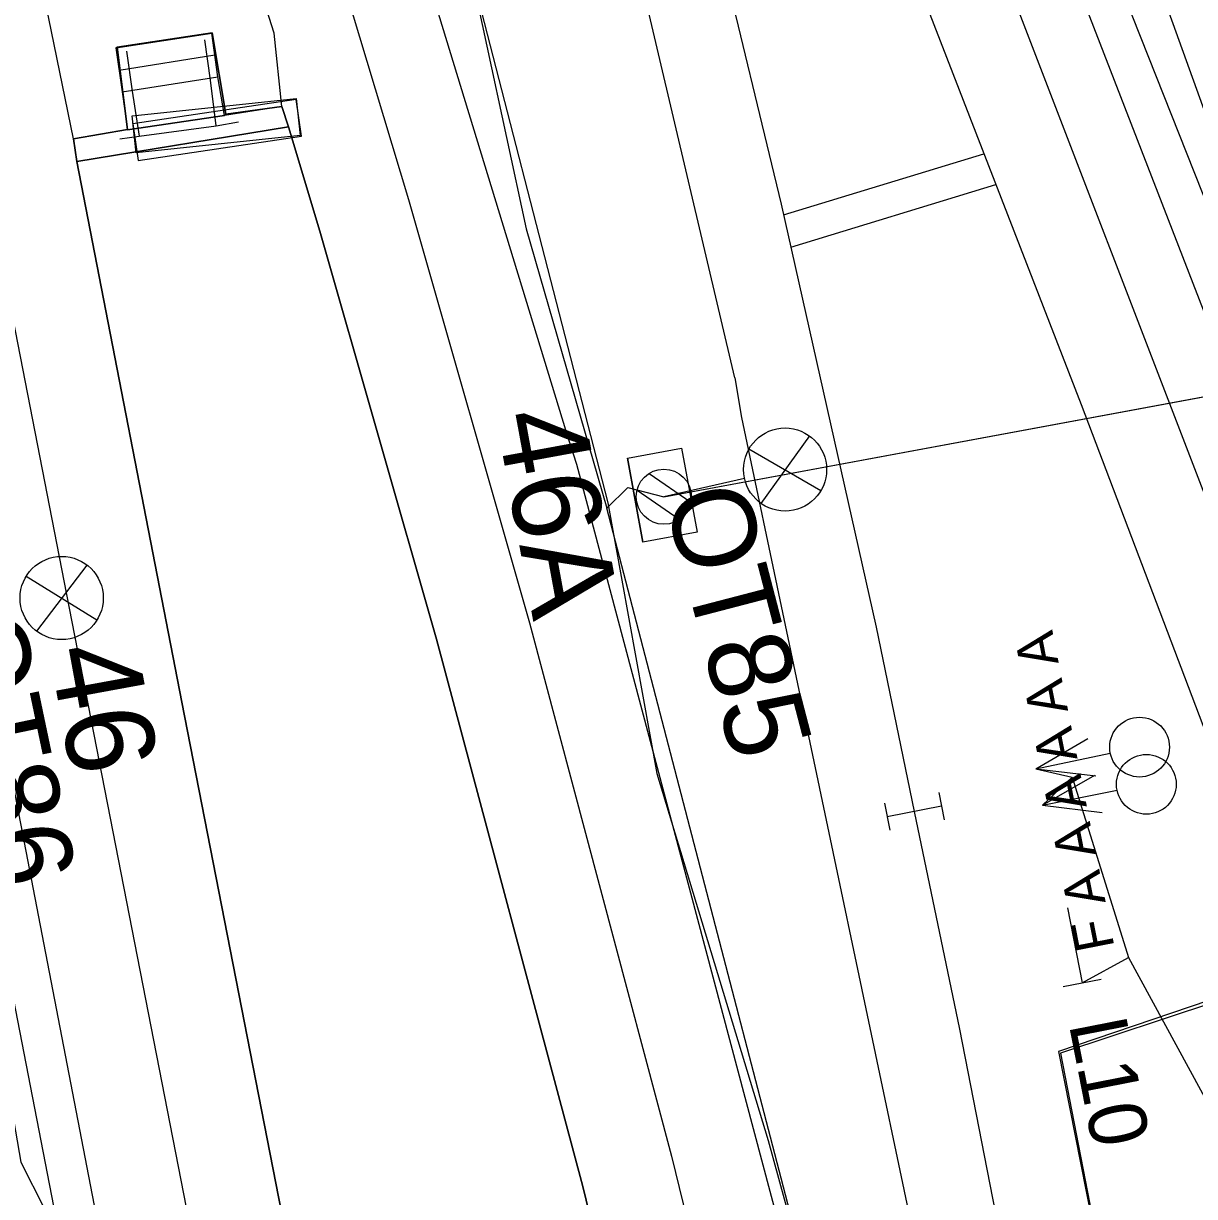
# Model space of a CAD drawing. Extents: x -545736 to -544888, y -1122892 to -1119128.
# Drawn here: x -545201.67 to -545180.42, y -1121712.96 to -1121691.68 of the extents above; entities that cross this region are included whole.
import ezdxf

# ---------------------------------------------------------------- set-up
doc = ezdxf.new("R2010")
doc.units = 0
for name, color, linetype in [('osvětlené plochy-hodnota-obrys', 7, 'Continuous'), ('Podbarveni_Komunikace', 7, 'Continuous'), ('Podbarveni_Nastupiste', 7, 'Continuous'), ('Vrstva 1 - Koleje', 7, 'Continuous'), ('Vrstva 11 - Trakce', 7, 'Continuous'), ('Vrstva 12 - Trakce zaklady', 7, 'Continuous'), ('Vrstva 13', 7, 'Continuous'), ('Vrstva 14_zastreseni a nastupiste', 7, 'Continuous'), ('Vrstva 16_plochy', 7, 'Continuous'), ('Vrstva 17_ploty - zabradli', 7, 'Continuous'), ('Vrstva 23 - PHS - pozemni - schody - eskalatory', 7, 'Continuous'), ('Vrstva 25', 7, 'Continuous'), ('Vrstva 26', 7, 'Continuous'), ('Vrstva 28 - zabzar', 7, 'Continuous'), ('Vrstva 3 - Lisy - Pocitaci body', 7, 'Continuous'), ('Vrstva 4 - Teren - stezky - prechody - plochy', 7, 'Continuous'), ('Vrstva 44', 7, 'Continuous'), ('Vrstva 6 - Navesti', 7, 'Continuous'), ('Vrstva 7 - Namezniky-vystroj', 7, 'Continuous')]:
    doc.layers.add(name, color=color, linetype=linetype)

msp = doc.modelspace()

# ---------------------------------------------------------------- linework, layer by layer
at = {"layer": 'osvětlené plochy-hodnota-obrys'}
msp.add_lwpolyline([(-545137.864, -1121889.42), (-545168.59, -1121731.992), (-545178.308, -1121699.721), (-545197.027, -1121652.528), (-545208.16, -1121619.35), (-545217.952, -1121591.114), (-545225.649, -1121565.547)], dxfattribs=at)
at = {"layer": 'Podbarveni_Komunikace'}
msp.add_lwpolyline([(-545180.039, -1121709.428), (-545180.163, -1121709.404), (-545182.89, -1121710.328), (-545181.985, -1121714.917)], dxfattribs=at)
at = {"layer": 'Podbarveni_Nastupiste'}
for p, q in [((-545196.294, -1121695.448), (-545196.861, -1121693.551)), ((-545194.179, -1121702.847), (-545196.294, -1121695.448)), ((-545198.798, -1121703.988), (-545196.89, -1121713.766))]:
    msp.add_line(p, q, dxfattribs=at)
for points in [[(-545196.861, -1121693.551), (-545200.703, -1121694.182), (-545198.798, -1121703.988)], [(-545189.161, -1121722.457), (-545191.523, -1121712.775), (-545194.179, -1121702.847)]]:
    msp.add_lwpolyline(points, dxfattribs=at)
at = {"layer": 'Vrstva 1 - Koleje'}
for points in [[(-545204.598, -1121683.045), (-545202.446, -1121694.084), (-545200.893, -1121702.036), (-545198.518, -1121714.179), (-545196.602, -1121723.995), (-545194.695, -1121733.769), (-545192.79, -1121743.532), (-545190.869, -1121753.385), (-545188.974, -1121763.101), (-545187.053, -1121772.965), (-545185.151, -1121782.729), (-545183.231, -1121792.594), (-545181.323, -1121802.379), (-545179.426, -1121812.108), (-545177.532, -1121821.821), (-545175.608, -1121831.705), (-545173.691, -1121841.53), (-545171.796, -1121851.251), (-545169.872, -1121861.126)], [(-545190.187, -1121685.59), (-545187.923, -1121694.959), (-545186.2, -1121702.627), (-545185.507, -1121705.971), (-545184.687, -1121709.924), (-545182.492, -1121721.163), (-545180.59, -1121730.931), (-545178.666, -1121740.784), (-545176.766, -1121750.544), (-545174.869, -1121760.278), (-545172.942, -1121770.162), (-545171.042, -1121779.908), (-545169.129, -1121789.7), (-545167.212, -1121799.555), (-545165.293, -1121809.36), (-545163.388, -1121819.134), (-545161.468, -1121828.982), (-545159.566, -1121838.742), (-545157.655, -1121848.546), (-545155.739, -1121858.373)], [(-545196.328, -1121689.408), (-545194.686, -1121694.87), (-545192.492, -1121702.549), (-545189.916, -1121712.225), (-545187.524, -1121721.986), (-545185.303, -1121731.906), (-545183.337, -1121741.604), (-545181.431, -1121751.413), (-545179.514, -1121761.238), (-545177.608, -1121771.007), (-545175.701, -1121780.793), (-545173.785, -1121790.62), (-545171.889, -1121800.35), (-545169.976, -1121810.166), (-545168.071, -1121819.938), (-545166.148, -1121829.808), (-545164.234, -1121839.613), (-545162.332, -1121849.377), (-545160.421, -1121859.17)], [(-545185.383, -1121691.101), (-545182.479, -1121698.59), (-545179.623, -1121706.109), (-545177.117, -1121713.199), (-545175.826, -1121717.114), (-545175.044, -1121719.485), (-545172.193, -1121729.1), (-545169.655, -1121738.82), (-545167.452, -1121748.582), (-545165.503, -1121758.451), (-545163.6, -1121768.21), (-545161.69, -1121777.988), (-545159.773, -1121787.837), (-545157.871, -1121797.594), (-545155.965, -1121807.383), (-545154.069, -1121817.086), (-545152.127, -1121827.047), (-545150.241, -1121836.711), (-545148.328, -1121846.526), (-545146.419, -1121856.308)]]:
    msp.add_lwpolyline(points, dxfattribs=at)
at = {"layer": 'Vrstva 11 - Trakce'}
for p, q in [((-545190.052, -1121700.262), (-545169.358, -1121696.433)), ((-545190.316, -1121699.842), (-545189.564, -1121700.36)), ((-545190.535, -1121700.146), (-545189.772, -1121700.672))]:
    msp.add_line(p, q, dxfattribs=at)
msp.add_circle((-545190.052, -1121700.262), 0.5, dxfattribs=at)
at = {"layer": 'Vrstva 12 - Trakce zaklady'}
for p, q in [((-545190.714, -1121699.563), (-545189.73, -1121699.382)), ((-545189.45, -1121700.906), (-545190.434, -1121701.087))]:
    msp.add_line(p, q, dxfattribs=at)
for points in [[(-545189.73, -1121699.382), (-545189.45, -1121700.906), (-545190.434, -1121701.087), (-545190.714, -1121699.563), (-545189.73, -1121699.382)], [(-545189.73, -1121699.382), (-545189.73, -1121699.382), (-545189.45, -1121700.906), (-545189.45, -1121700.906)], [(-545190.714, -1121699.563), (-545190.714, -1121699.563), (-545190.434, -1121701.087), (-545190.434, -1121701.087)]]:
    msp.add_lwpolyline(points, dxfattribs=at)
at = {"layer": 'Vrstva 13'}
for p, q in [((-545196.981, -1121693.185), (-545196.986, -1121693.19)), ((-545196.861, -1121693.551), (-545196.861, -1121693.551)), ((-545200.766, -1121693.77), (-545200.766, -1121693.77)), ((-545200.703, -1121694.182), (-545200.703, -1121694.182))]:
    msp.add_line(p, q, dxfattribs=at)
msp.add_lwpolyline([(-545200.703, -1121694.182), (-545196.861, -1121693.551), (-545196.981, -1121693.185), (-545198.025, -1121693.349), (-545199.783, -1121693.61), (-545200.766, -1121693.77)], close=True, dxfattribs=at)
for points in [[(-545198.025, -1121693.349), (-545198.002, -1121693.324), (-545196.981, -1121693.185), (-545196.861, -1121693.551)], [(-545200.703, -1121694.182), (-545200.766, -1121693.77), (-545199.786, -1121693.603), (-545199.783, -1121693.61)]]:
    msp.add_lwpolyline(points, dxfattribs=at)
at = {"layer": 'Vrstva 14_zastreseni a nastupiste'}
for p, q in [((-545196.861, -1121693.551), (-545196.861, -1121693.551)), ((-545200.703, -1121694.182), (-545200.703, -1121694.182))]:
    msp.add_line(p, q, dxfattribs=at)
msp.add_lwpolyline([(-545189.242, -1121752.936), (-545191.158, -1121743.114), (-545193.062, -1121733.349), (-545194.982, -1121723.565), (-545196.89, -1121713.766), (-545198.798, -1121703.988), (-545200.703, -1121694.182), (-545196.861, -1121693.551), (-545196.294, -1121695.448), (-545194.179, -1121702.847), (-545191.523, -1121712.775), (-545189.161, -1121722.457), (-545186.979, -1121732.216), (-545185.006, -1121741.979), (-545183.088, -1121751.748)], dxfattribs=at)
msp.add_lwpolyline([(-545189.242, -1121752.936), (-545191.158, -1121743.114), (-545193.062, -1121733.349), (-545194.982, -1121723.565), (-545196.89, -1121713.766), (-545198.798, -1121703.988), (-545200.703, -1121694.182), (-545196.861, -1121693.551), (-545196.294, -1121695.448), (-545194.179, -1121702.847), (-545191.523, -1121712.775), (-545189.161, -1121722.457), (-545186.979, -1121732.216), (-545185.006, -1121741.979), (-545183.088, -1121751.748)], dxfattribs=at)
at = {"layer": 'Vrstva 16_plochy'}
for points in [[(-545189.242, -1121752.936), (-545191.158, -1121743.114), (-545193.062, -1121733.349), (-545194.982, -1121723.565), (-545196.89, -1121713.766), (-545198.798, -1121703.988), (-545200.703, -1121694.182), (-545196.861, -1121693.551), (-545196.294, -1121695.448), (-545194.179, -1121702.847), (-545191.523, -1121712.775), (-545189.161, -1121722.457), (-545186.979, -1121732.216), (-545185.006, -1121741.979), (-545183.088, -1121751.748)], [(-545181.959, -1121714.966), (-545178.683, -1121714.378), (-545179.201, -1121712.924), (-545178.847, -1121712.802), (-545180.039, -1121709.428), (-545182.857, -1121710.357), (-545181.959, -1121714.966)]]:
    msp.add_lwpolyline(points, dxfattribs=at)
at = {"layer": 'Vrstva 17_ploty - zabradli'}
for p, q in [((-545198.175, -1121693.533), (-545197.772, -1121693.465)), ((-545199.922, -1121693.769), (-545199.574, -1121693.722)), ((-545199.574, -1121693.722), (-545198.175, -1121693.533))]:
    msp.add_line(p, q, dxfattribs=at)
for points in [[(-545198.175, -1121693.533), (-545198.278, -1121692.704), (-545198.384, -1121691.977)], [(-545199.802, -1121692.178), (-545199.699, -1121692.908), (-545199.574, -1121693.722)]]:
    msp.add_lwpolyline(points, dxfattribs=at)
at = {"layer": 'Vrstva 23 - PHS - pozemni - schody - eskalatory'}
for p, q in [((-545199.994, -1121692.121), (-545198.253, -1121691.857)), ((-545199.879, -1121692.916), (-545198.143, -1121692.647))]:
    msp.add_line(p, q, dxfattribs=at)
for points in [[(-545199.783, -1121693.61), (-545198.025, -1121693.349), (-545198.143, -1121692.647), (-545198.253, -1121691.857), (-545198.246, -1121691.849), (-545199.971, -1121692.109)], [(-545198.025, -1121693.349), (-545198.002, -1121693.324), (-545198.246, -1121691.849)], [(-545199.971, -1121692.109), (-545199.994, -1121692.121), (-545199.879, -1121692.916), (-545199.783, -1121693.61)], [(-545199.783, -1121693.61), (-545199.786, -1121693.603), (-545199.971, -1121692.109)], [(-545198.198, -1121692.255), (-545199.935, -1121692.531)]]:
    msp.add_lwpolyline(points, dxfattribs=at)
for points in [[(-545196.722, -1121693.037), (-545196.65, -1121693.709), (-545199.629, -1121694.027), (-545199.701, -1121693.355)], [(-545196.624, -1121693.725), (-545196.724, -1121693.057), (-545199.687, -1121693.497), (-545199.588, -1121694.165)]]:
    msp.add_lwpolyline(points, close=True, dxfattribs=at)
at = {"layer": 'Vrstva 25'}
for p, q in [((-545187.41, -1121699.16), (-545188.289, -1121700.385)), ((-545187.203, -1121700.154), (-545188.509, -1121699.399)), ((-545188.588, -1121699.933), (-545190.052, -1121700.262)), ((-545200.52, -1121701.503), (-545201.433, -1121702.702)), ((-545200.341, -1121702.502), (-545201.625, -1121701.71))]:
    msp.add_line(p, q, dxfattribs=at)
msp.add_lwpolyline([(-545190.052, -1121700.262), (-545169.358, -1121696.433)], dxfattribs=at)
for centre in [(-545187.852, -1121699.77), (-545200.979, -1121702.1)]:
    msp.add_circle(centre, 0.754, dxfattribs=at)
at = {"layer": 'Vrstva 26'}
for points in [[(-545201.519, -1121666.737), (-545194.694, -1121685.456), (-545192.548, -1121695.403), (-545191.089, -1121700.472), (-545190.706, -1121700.096), (-545190.052, -1121700.262)], [(-545175.347, -1121736.419), (-545175.635, -1121736.453), (-545176.212, -1121734.774), (-545181.811, -1121735.952), (-545182.224, -1121732.257), (-545186.143, -1121719.457), (-545191.089, -1121700.472)], [(-545203.192, -1121702.53), (-545203.229, -1121702.296), (-545203.64, -1121702.489), (-545202.416, -1121708.322), (-545201.721, -1121712.334), (-545201.289, -1121713.182), (-545198.256, -1121728.49), (-545197.89, -1121732.404), (-545197.312, -1121733.586), (-545196.305, -1121738.106), (-545182.383, -1121735.328), (-545181.811, -1121735.952)]]:
    msp.add_lwpolyline(points, dxfattribs=at)
at = {"layer": 'Vrstva 28 - zabzar'}
msp.add_line((-545182.46, -1121709.08), (-545181.62, -1121708.62), dxfattribs=at)
for points in [[(-545183.3, -1121705.2), (-545182.64, -1121705.35), (-545183.18, -1121705.86)], [(-545182.64, -1121705.35), (-545181.62, -1121708.62), (-545180.09, -1121711.43)]]:
    msp.add_lwpolyline(points, dxfattribs=at)
at = {"layer": 'Vrstva 3 - Lisy - Pocitaci body'}
for p, q in [((-545183.3, -1121705.2), (-545182.359, -1121704.649)), ((-545183.3, -1121705.2), (-545181.95, -1121704.915)), ((-545183.3, -1121705.2), (-545182.216, -1121705.324)), ((-545183.18, -1121705.86), (-545182.234, -1121705.316)), ((-545185.064, -1121705.63), (-545184.968, -1121706.121)), ((-545183.18, -1121705.86), (-545181.828, -1121705.585)), ((-545186.046, -1121705.821), (-545185.95, -1121706.312)), ((-545185.016, -1121705.875), (-545185.998, -1121706.067)), ((-545183.18, -1121705.86), (-545182.097, -1121705.992))]:
    msp.add_line(p, q, dxfattribs=at)
for centre in [(-545181.419, -1121704.805), (-545181.296, -1121705.479)]:
    msp.add_circle(centre, 0.542, dxfattribs=at)
at = {"layer": 'Vrstva 4 - Teren - stezky - prechody - plochy'}
for points in [[(-545188.763, -1121698.109), (-545190.715, -1121689.813), (-545195.065, -1121673.326), (-545198.286, -1121662.387), (-545202.669, -1121648.347), (-545213.282, -1121617.261), (-545221.968, -1121591.293), (-545228.066, -1121573.381), (-545232.36, -1121560.669), (-545237.333, -1121545.795), (-545240.195, -1121536.787), (-545241.095, -1121537.02)], [(-545191.805, -1121699.137), (-545194.474, -1121690.403), (-545196.452, -1121683.768), (-545199.249, -1121675.317), (-545202.803, -1121664.861), (-545207.816, -1121650.626), (-545217.94, -1121619.813), (-545226.341, -1121592.264), (-545232.146, -1121573.195), (-545235.937, -1121558.858), (-545238.806, -1121546.877), (-545241.095, -1121537.02)], [(-545177.153, -1121708.388), (-545177.337, -1121707.756), (-545186.682, -1121683.465), (-545192.636, -1121667.775), (-545200.255, -1121645.889), (-545203.013, -1121638.235), (-545202.124, -1121637.845)], [(-545177.153, -1121708.388), (-545175.107, -1121707.611), (-545175.507, -1121706.398), (-545184.454, -1121681.584), (-545189.524, -1121667.292), (-545194.023, -1121655.906), (-545198.205, -1121646.356), (-545202.124, -1121637.845)], [(-545200.766, -1121693.77), (-545199.786, -1121693.603), (-545199.971, -1121692.109), (-545198.246, -1121691.849), (-545198.002, -1121693.324), (-545196.981, -1121693.185), (-545197.124, -1121691.857), (-545199.462, -1121684.52), (-545202.574, -1121675.254), (-545205.037, -1121667.713), (-545205.972, -1121668.035)], [(-545200.766, -1121693.77), (-545203.014, -1121682.821), (-545204.237, -1121675.848), (-545205.972, -1121668.035)], [(-545183.088, -1121751.748), (-545185.006, -1121741.979), (-545186.979, -1121732.216), (-545189.161, -1121722.457), (-545191.523, -1121712.775), (-545194.179, -1121702.847), (-545196.294, -1121695.448), (-545196.861, -1121693.551), (-545196.981, -1121693.185), (-545198.002, -1121693.324), (-545198.246, -1121691.849), (-545199.971, -1121692.109), (-545199.786, -1121693.603), (-545200.766, -1121693.77), (-545200.703, -1121694.182), (-545198.798, -1121703.988), (-545196.89, -1121713.766), (-545194.982, -1121723.565), (-545193.062, -1121733.349), (-545191.158, -1121743.114), (-545189.242, -1121752.936)], [(-545188.763, -1121698.109), (-545188.641, -1121698.826), (-545185.213, -1121715.136), (-545181.647, -1121733.399), (-545177.117, -1121756.524), (-545170.416, -1121791.087), (-545164.311, -1121822.524), (-545157.023, -1121859.828), (-545149.915, -1121896.158), (-545142.13, -1121936.158), (-545141.676, -1121939.159), (-545141.157, -1121942.596), (-545141.923, -1121943.776)], [(-545141.923, -1121943.776), (-545142.097, -1121942.982), (-545141.665, -1121942.659), (-545141.923, -1121941.346), (-545142.767, -1121941.354), (-545151.586, -1121896.379), (-545158.808, -1121859.367), (-545165.97, -1121822.744), (-545172.05, -1121791.327), (-545183.361, -1121733.476), (-545187.416, -1121715.505), (-545191.632, -1121699.681), (-545191.805, -1121699.137)], [(-545146.11, -1122004.734), (-545145.37, -1122004.712), (-545146.573, -1121994.03), (-545148.01, -1121983.54), (-545148.508, -1121980.262), (-545148.842, -1121978.248), (-545150.866, -1121967.009), (-545156.33, -1121939.097), (-545168.64, -1121875.718), (-545175.381, -1121841.399), (-545180.031, -1121817.339), (-545184.955, -1121792.055), (-545193.253, -1121749.702), (-545199.085, -1121719.832), (-545202.547, -1121701.925)], [(-545180.039, -1121709.428), (-545180.163, -1121709.404), (-545182.89, -1121710.328), (-545181.985, -1121714.917), (-545180.848, -1121720.815), (-545179.628, -1121726.7), (-545177.717, -1121736.49), (-545175.814, -1121746.279), (-545173.137, -1121759.988), (-545171.232, -1121769.763), (-545170.096, -1121775.61), (-545168.189, -1121785.44), (-545166.652, -1121793.283), (-545164.749, -1121803.058), (-545162.839, -1121812.848), (-545160.922, -1121822.667), (-545159.009, -1121832.498), (-545157.103, -1121842.273), (-545155.195, -1121852.046), (-545153.289, -1121861.829)]]:
    msp.add_lwpolyline(points, dxfattribs=at)
at = {"layer": 'Vrstva 44'}
for points in [[(-545206.107, -1121653.28), (-545195.07, -1121685.376), (-545195.061, -1121685.517), (-545194.992, -1121685.612), (-545194.193, -1121688.229), (-545191.066, -1121700.374), (-545190.181, -1121705.285), (-545188.159, -1121711.939), (-545183.274, -1121729.753), (-545183.103, -1121729.934)], [(-545139.779, -1121877.836), (-545147.175, -1121839.811), (-545147.369, -1121839.002), (-545147.437, -1121838.152), (-545155.452, -1121797.558), (-545155.595, -1121796.474), (-545155.658, -1121796.154), (-545157.036, -1121788.893), (-545157.839, -1121784.658), (-545161.523, -1121765.245), (-545161.723, -1121764.693), (-545161.769, -1121763.91), (-545164.033, -1121753.897), (-545169.852, -1121728.16), (-545170.129, -1121727.27), (-545170.396, -1121726.56), (-545170.338, -1121725.182), (-545172.293, -1121718.704), (-545175.993, -1121707.957), (-545178.907, -1121700.544), (-545179.343, -1121699.618), (-545179.583, -1121698.628), (-545193.322, -1121663.167)], [(-545202.821, -1121704.433), (-545197.443, -1121732.122), (-545197.31, -1121732.52)]]:
    msp.add_lwpolyline(points, dxfattribs=at)
at = {"layer": 'Vrstva 6 - Navesti'}
for p, q in [((-545182.727, -1121707.72), (-545182.46, -1121709.08)), ((-545182.803, -1121709.147), (-545182.117, -1121709.013))]:
    msp.add_line(p, q, dxfattribs=at)
at = {"layer": 'Vrstva 7 - Namezniky-vystroj'}
for p, q in [((-545187.881, -1121695.147), (-545184.243, -1121694.04)), ((-545187.749, -1121695.734), (-545184.026, -1121694.601))]:
    msp.add_line(p, q, dxfattribs=at)

# ---------------------------------------------------------------- texts
at = {"layer": 'Vrstva 11 - Trakce'}
for s, p in [('46A', (-545193.107, -1121698.795)), ('46', (-545201.213, -1121703.05))]:
    msp.add_text(s, height=1.6, rotation=280.4107, dxfattribs=at).set_placement(p)
at = {"layer": 'Vrstva 25'}
for s, rotation, p in [('OT85', 284.6022, (-545190.052, -1121700.262)), ('OT86', 281.851, (-545203.192, -1121702.53))]:
    msp.add_text(s, height=1.5, rotation=rotation, dxfattribs=at).set_placement(p)
at = {"layer": 'Vrstva 6 - Navesti'}
for s, height, rotation, p in [('  F A A A A A A ', 0.7, 101.1079, (-545181.773, -1121708.945)), ('L10', 1.05, 281.1079, (-545182.705, -1121709.825))]:
    msp.add_text(s, height=height, rotation=rotation, dxfattribs=at).set_placement(p)

doc.saveas('drawing.dxf')
